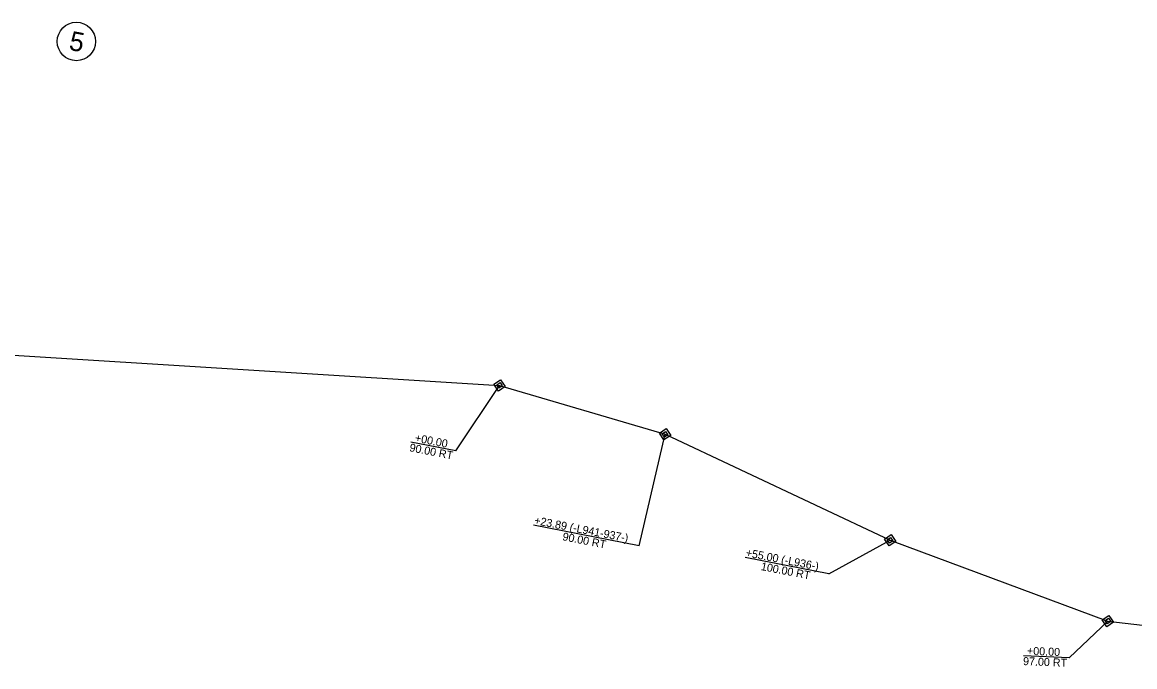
# Model space of a CAD drawing. Extents: x 1002576 to 1014655, y 551673 to 557994.
# Drawn here: x 1013330 to 1014025, y 551997 to 552400 of the extents above; entities that cross this region are included whole.
import ezdxf

# ---------------------------------------------------------------- set-up
doc = ezdxf.new("R2010")
doc.units = 0
for name, color, linetype in [('Exist Hydro Stream or Body of Water', 7, 'Continuous'), ('Exist Other Culture Area Outline', 7, 'Continuous'), ('Exist Roads EOP Other', 7, 'Continuous'), ('Exist Structure Major Deck Tunnel Box Culvert', 7, 'Continuous'), ('Exist Utilities Power Pole CELL', 7, 'Continuous')]:
    doc.layers.add(name, color=color, linetype=linetype)

msp = doc.modelspace()

# ---------------------------------------------------------------- linework, layer by layer
at = {"layer": 'Exist Hydro Stream or Body of Water'}
for p, q in [((1013628.1, 552173.01), (1013628.1, 552173.01)), ((1013731.51, 552142.48), (1013731.51, 552142.48)), ((1013872.04, 552076.32), (1013872.04, 552076.32)), ((1014008.03, 552025.92), (1014008.03, 552025.92))]:
    msp.add_line(p, q, dxfattribs=at)
at = {"layer": 'Exist Other Culture Area Outline'}
for p, q in [((1013102.95, 552205.62), (1013628.1, 552173.01)), ((1013628.1, 552173.01), (1013731.51, 552142.48)), ((1013731.51, 552142.48), (1013872.04, 552076.32)), ((1013872.04, 552076.32), (1014008.03, 552025.92)), ((1014008.03, 552025.92), (1014188.95, 552004.91))]:
    msp.add_line(p, q, dxfattribs=at)
at = {"layer": 'Exist Roads EOP Other'}
for p, q in [((1013600.87, 552132.14), (1013572.69, 552137.61)), ((1013715.28, 552072.92), (1013649.39, 552085.71)), ((1013833.71, 552055.39), (1013781.5, 552065.53)), ((1013983.93, 552003.04), (1013955.24, 552004.21))]:
    msp.add_line(p, q, dxfattribs=at)
for points in [[(1013600.87, 552132.14), (1013628.1, 552173.01)], [(1013715.28, 552072.92), (1013731.51, 552142.48)], [(1013833.71, 552055.39), (1013872.04, 552076.32)], [(1013983.93, 552003.04), (1014008.03, 552025.92)]]:
    msp.add_lwpolyline(points, dxfattribs=at)
at = {"layer": 'Exist Structure Major Deck Tunnel Box Culvert'}
for points in [[(1013631.63, 552172.32), (1013627.41, 552169.47), (1013624.56, 552173.69), (1013628.78, 552176.54)], [(1013629.86, 552172.66), (1013627.75, 552171.24), (1013626.33, 552173.35), (1013628.44, 552174.77)], [(1013735.04, 552141.79), (1013730.82, 552138.94), (1013727.97, 552143.16), (1013732.19, 552146.01)], [(1013733.27, 552142.13), (1013731.16, 552140.71), (1013729.74, 552142.82), (1013731.85, 552144.24)], [(1013875.57, 552075.63), (1013871.35, 552072.79), (1013868.5, 552077.01), (1013872.72, 552079.85)], [(1013873.8, 552075.98), (1013871.69, 552074.55), (1013870.27, 552076.66), (1013872.38, 552078.09)], [(1014011.56, 552025.24), (1014007.34, 552022.39), (1014004.5, 552026.61), (1014008.71, 552029.46)], [(1014009.8, 552025.58), (1014007.69, 552024.16), (1014006.26, 552026.27), (1014008.37, 552027.69)]]:
    msp.add_lwpolyline(points, close=True, dxfattribs=at)
at = {"layer": 'Exist Utilities Power Pole CELL'}
msp.add_line((1013363.86, 552387.66), (1013363.86, 552387.66), dxfattribs=at)
msp.add_circle((1013363.86, 552387.66), 12, dxfattribs=at)

# ---------------------------------------------------------------- texts
at = {"layer": 'Exist Roads EOP Other'}
for s, rotation, p in [('+00.00', 349.01724, (1013574.98, 552137.96)), ('90.00 RT', 349.01724, (1013571.57, 552131.94)), ('+23.89 (-L941-937-)', 349.01724, (1013649.47, 552086.49)), ('90.00 RT', 349.01724, (1013667.12, 552076.38)), ('+55.00 (-L936-)', 349.01724, (1013781.58, 552066.3)), ('100.00 RT', 349.01724, (1013791.04, 552057.79)), ('97.00 RT', 357.67072, (1013954.99, 551998.44)), ('+00.00', 357.67072, (1013957.45, 552004.89))]:
    msp.add_text(s, height=5, rotation=rotation, dxfattribs=at).set_placement(p)
at = {"layer": 'Exist Utilities Power Pole CELL'}
msp.add_text('5', height=12, rotation=349.01724, dxfattribs=at).set_placement((1013358.72, 552382.55))

doc.saveas('drawing.dxf')
